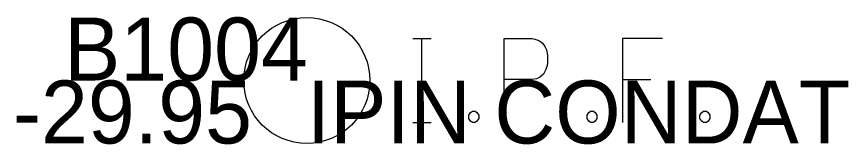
# Model space of a CAD drawing. Extents: x 2177554 to 2180444, y 721535 to 723442.
# Drawn here: x 2177553.845 to 2177554.636, y 721628.903 to 721629.025 of the extents above; entities that cross this region are included whole.
import ezdxf

# ---------------------------------------------------------------- set-up
doc = ezdxf.new("R2010")
doc.units = 0
for name, color, linetype in [('SV_X_Mon_Cells_Found', 7, 'Continuous'), ('SV_X_Text_Comment', 7, 'Continuous'), ('SV_X_Text_Elevation', 7, 'Continuous'), ('SV_X_Text_Name', 7, 'Continuous')]:
    doc.layers.add(name, color=color, linetype=linetype)

msp = doc.modelspace()

# ---------------------------------------------------------------- linework, layer by layer
at = {"layer": 'SV_X_Mon_Cells_Found'}
for points in [[(2177554.22172, 721629.004), (2177554.23936, 721629.004)], [(2177554.23054, 721628.924), (2177554.23054, 721629.004)], [(2177554.3088, 721628.924), (2177554.3088, 721629.004), (2177554.33526, 721629.004), (2177554.33802, 721629.00337), (2177554.34187, 721629.00211), (2177554.34353, 721629.00085), (2177554.34518, 721628.99959), (2177554.34738, 721628.99644), (2177554.34904, 721628.99329), (2177554.35014, 721628.98825), (2177554.35014, 721628.98069), (2177554.34959, 721628.97817), (2177554.34848, 721628.97439), (2177554.34628, 721628.96999), (2177554.34407, 721628.96809), (2177554.34242, 721628.96683), (2177554.33966, 721628.96557), (2177554.33526, 721628.96495), (2177554.3088, 721628.96495)], [(2177554.45927, 721629.004), (2177554.42123, 721629.004), (2177554.42123, 721628.924)], [(2177554.42123, 721628.96495), (2177554.44824, 721628.96495)], [(2177554.27849, 721628.93471), (2177554.28124, 721628.93471), (2177554.2829, 721628.93345), (2177554.28455, 721628.93093), (2177554.28455, 721628.92778), (2177554.2829, 721628.92526), (2177554.28124, 721628.924), (2177554.27849, 721628.924), (2177554.27683, 721628.92526), (2177554.27518, 721628.92778), (2177554.27518, 721628.93093), (2177554.27683, 721628.93345), (2177554.27849, 721628.93471)], [(2177554.39093, 721628.93471), (2177554.39368, 721628.93471), (2177554.39533, 721628.93345), (2177554.39698, 721628.93093), (2177554.39698, 721628.92778), (2177554.39533, 721628.92526), (2177554.39368, 721628.924), (2177554.39093, 721628.924), (2177554.38927, 721628.92526), (2177554.38762, 721628.92778), (2177554.38762, 721628.93093), (2177554.38927, 721628.93345), (2177554.39093, 721628.93471)], [(2177554.49839, 721628.93471), (2177554.50115, 721628.93471), (2177554.5028, 721628.93345), (2177554.50445, 721628.93093), (2177554.50445, 721628.92778), (2177554.5028, 721628.92526), (2177554.50115, 721628.924), (2177554.49839, 721628.924), (2177554.49674, 721628.92526), (2177554.49509, 721628.92778), (2177554.49509, 721628.93093), (2177554.49674, 721628.93345), (2177554.49839, 721628.93471)], [(2177554.22172, 721628.924), (2177554.23936, 721628.924)]]:
    msp.add_lwpolyline(points, dxfattribs=at)
msp.add_circle((2177554.121, 721628.964), 0.06, dxfattribs=at)

# ---------------------------------------------------------------- texts
at = {"layer": 'SV_X_Text_Comment'}
msp.add_text('IPIN CONDAT', height=0.06, dxfattribs=at).set_placement((2177554.121, 721628.904))
at = {"layer": 'SV_X_Text_Elevation'}
msp.add_text('-29.95', height=0.06, dxfattribs=at).set_placement((2177553.84134, 721628.904))
at = {"layer": 'SV_X_Text_Name'}
msp.add_text('B1004', height=0.06, dxfattribs=at).set_placement((2177553.89002, 721628.964))

doc.saveas('drawing.dxf')
